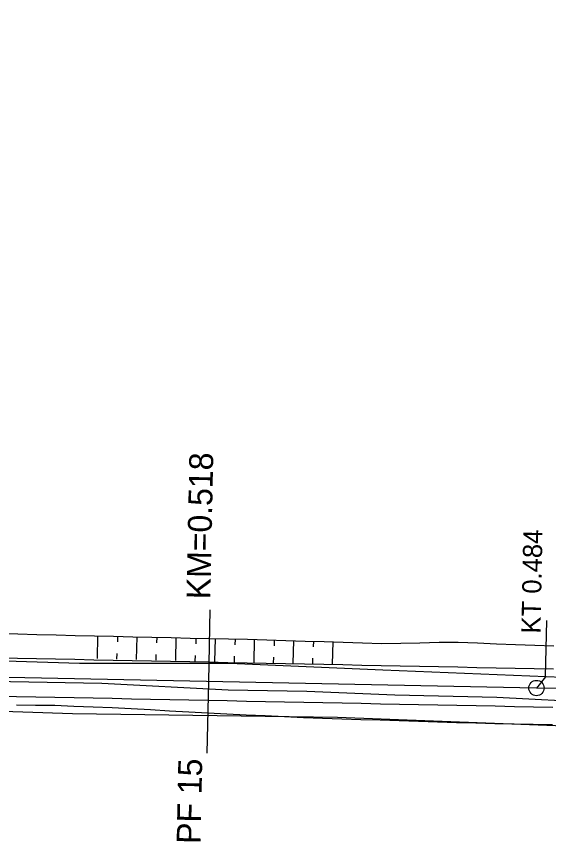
# Model space of a CAD drawing. Extents: x -478000 to -474772, y -1116940 to -1114124.
# Drawn here: x -477765.6 to -477710.1, y -1116657.5 to -1116571.3 of the extents above; entities that cross this region are included whole.
import ezdxf

# ---------------------------------------------------------------- set-up
doc = ezdxf.new("R2010")
doc.units = 0
for name, color, linetype in [('hrana_P', 7, 'Continuous'), ('L', 7, 'Continuous'), ('POLYGONY_SITUACE_PF', 7, 'Continuous'), ('POLYGONY_SITUACE_PF_POPISY', 7, 'Continuous'), ('POLYGONY_SITUACE_PO', 7, 'Continuous')]:
    doc.layers.add(name, color=color, linetype=linetype)

msp = doc.modelspace()

# ---------------------------------------------------------------- linework, layer by layer
for points in [[(-477710.3903956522, -1116640.33018744), (-477710.27233809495, -1116634.436584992)], [(-477710.3903956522, -1116640.33018744), (-477711.3429067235, -1116641.4972349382)]]:
    msp.add_lwpolyline(points)
at = {"layer": 'hrana_P'}
for p, q in [((-477765.65400000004, -1116643.2720000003), (-477763.65300000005, -1116643.287)), ((-477763.65300000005, -1116643.287), (-477761.65300000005, -1116643.2990000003)), ((-477761.65300000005, -1116643.2990000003), (-477759.655, -1116643.389)), ((-477759.655, -1116643.389), (-477757.656, -1116643.466)), ((-477757.656, -1116643.466), (-477755.657, -1116643.531)), ((-477755.657, -1116643.531), (-477753.65900000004, -1116643.642)), ((-477753.65900000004, -1116643.642), (-477751.66000000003, -1116643.755)), ((-477751.66000000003, -1116643.755), (-477749.662, -1116643.8660000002)), ((-477749.662, -1116643.8660000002), (-477747.66399999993, -1116643.975)), ((-477747.66399999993, -1116643.975), (-477745.666, -1116644.081)), ((-477745.666, -1116644.081), (-477743.66700000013, -1116644.186)), ((-477743.66700000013, -1116644.186), (-477741.669, -1116644.286)), ((-477741.669, -1116644.286), (-477739.67100000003, -1116644.386)), ((-477739.67100000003, -1116644.386), (-477737.672, -1116644.484)), ((-477737.672, -1116644.484), (-477735.673, -1116644.5620000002)), ((-477735.673, -1116644.5620000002), (-477733.6740000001, -1116644.6330000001)), ((-477733.6740000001, -1116644.6330000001), (-477731.6750000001, -1116644.703)), ((-477731.6750000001, -1116644.703), (-477729.67600000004, -1116644.7720000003)), ((-477729.67600000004, -1116644.7720000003), (-477727.677, -1116644.8390000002)), ((-477727.677, -1116644.8390000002), (-477725.67800000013, -1116644.905)), ((-477725.67800000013, -1116644.905), (-477723.6790000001, -1116644.969)), ((-477723.6790000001, -1116644.969), (-477721.68000000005, -1116645.031)), ((-477721.68000000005, -1116645.031), (-477719.68100000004, -1116645.0930000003)), ((-477719.68100000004, -1116645.0930000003), (-477717.68200000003, -1116645.151)), ((-477717.68200000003, -1116645.151), (-477715.68200000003, -1116645.209)), ((-477715.68200000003, -1116645.209), (-477713.683, -1116645.252)), ((-477713.683, -1116645.252), (-477711.683, -1116645.291)), ((-477711.683, -1116645.291), (-477709.6699999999, -1116645.3220000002))]:
    msp.add_line(p, q, dxfattribs=at)
for points in [[(-477767.504, -1116635.7890000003), (-477765.505, -1116635.842)], [(-477765.505, -1116635.842), (-477763.505, -1116635.896)], [(-477763.505, -1116635.896), (-477761.506, -1116635.948)], [(-477761.506, -1116635.948), (-477759.50700000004, -1116636)], [(-477759.50700000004, -1116636), (-477757.50700000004, -1116636.05)], [(-477757.50700000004, -1116636.05), (-477755.50800000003, -1116636.097)], [(-477757.2007821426, -1116638.425437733), (-477757.14059436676, -1116636.030824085)], [(-477755.50800000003, -1116636.097), (-477753.50800000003, -1116636.144)], [(-477755.09472800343, -1116636.08224622), (-477755.1097749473, -1116636.680899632)], [(-477753.50800000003, -1116636.144), (-477751.509, -1116636.1910000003)], [(-477753.1090494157, -1116638.528282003), (-477753.04886164, -1116636.133668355)], [(-477751.509, -1116636.1910000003), (-477749.509, -1116636.236)], [(-477751.00299527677, -1116636.18509049), (-477751.0180422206, -1116636.783743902)], [(-477749.509, -1116636.236), (-477747.51, -1116636.282)], [(-477749.017316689, -1116638.631126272), (-477748.95712891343, -1116636.236512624)], [(-477747.51, -1116636.282), (-477745.51, -1116636.326)], [(-477746.91126255, -1116636.287934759), (-477746.92630949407, -1116636.886588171)], [(-477745.51, -1116636.326), (-477743.511, -1116636.3660000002)], [(-477744.92558396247, -1116638.733970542), (-477744.86539618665, -1116636.339356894)], [(-477743.511, -1116636.3660000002), (-477741.51099999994, -1116636.406)], [(-477742.8195298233, -1116636.390779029), (-477742.8345767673, -1116636.9894324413)], [(-477741.51099999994, -1116636.406), (-477739.5120000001, -1116636.469)], [(-477740.8338512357, -1116638.836814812), (-477740.77366346, -1116636.442201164)], [(-477739.5120000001, -1116636.469), (-477737.51300000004, -1116636.531)], [(-477738.7277970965, -1116636.493623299), (-477738.7428440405, -1116637.0922767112)], [(-477737.51300000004, -1116636.531), (-477735.514, -1116636.5930000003)], [(-477736.74211850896, -1116638.939659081), (-477736.6819307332, -1116636.545045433)], [(-477735.514, -1116636.5930000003), (-477733.51500000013, -1116636.6540000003)], [(-477734.6360643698, -1116636.596467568), (-477734.65111131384, -1116637.19512098)], [(-477733.51500000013, -1116636.6540000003), (-477731.515, -1116636.7140000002)], [(-477732.6503857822, -1116639.042503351), (-477732.5901980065, -1116636.647889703)], [(-477731.515, -1116636.7140000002), (-477729.516, -1116636.774)], [(-477729.516, -1116636.774), (-477727.51699999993, -1116636.8330000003)], [(-477727.51699999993, -1116636.8330000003), (-477725.5160000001, -1116636.8160000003)], [(-477725.5160000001, -1116636.8160000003), (-477723.515, -1116636.7620000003)], [(-477723.515, -1116636.7620000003), (-477721.51300000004, -1116636.7070000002)], [(-477721.51300000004, -1116636.7070000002), (-477719.51300000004, -1116636.7080000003)], [(-477719.51300000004, -1116636.7080000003), (-477717.51400000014, -1116636.787)], [(-477717.51400000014, -1116636.787), (-477715.51500000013, -1116636.8660000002)], [(-477715.51500000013, -1116636.8660000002), (-477713.516, -1116636.944)], [(-477713.516, -1116636.944), (-477711.51800000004, -1116637.021)], [(-477711.51800000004, -1116637.021), (-477709.53400000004, -1116637.095)], [(-477765.55600000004, -1116638.411), (-477767.55600000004, -1116638.371)], [(-477763.5569999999, -1116638.451), (-477765.55600000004, -1116638.411)], [(-477761.55700000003, -1116638.4910000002), (-477763.5569999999, -1116638.451)], [(-477759.55700000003, -1116638.531), (-477761.55700000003, -1116638.4910000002)], [(-477757.558, -1116638.571), (-477759.55700000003, -1116638.531)], [(-477755.558, -1116638.611), (-477757.558, -1116638.571)], [(-477755.15491577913, -1116638.476859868), (-477755.1398688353, -1116637.878206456)], [(-477751.06318305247, -1116638.579704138), (-477751.04813610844, -1116637.981050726)], [(-477746.9714503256, -1116638.682548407), (-477746.9564033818, -1116638.0838949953)], [(-477742.879717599, -1116638.785392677), (-477742.86467065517, -1116638.1867392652)], [(-477738.78798487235, -1116638.888236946), (-477738.7729379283, -1116638.2895835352)], [(-477734.6962521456, -1116638.991081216), (-477734.6812052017, -1116638.392427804)], [(-477753.559, -1116638.651), (-477755.558, -1116638.611)], [(-477751.559, -1116638.6910000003), (-477753.559, -1116638.651)], [(-477749.5590000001, -1116638.7310000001), (-477751.559, -1116638.6910000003)], [(-477747.56, -1116638.771), (-477749.5590000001, -1116638.7310000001)], [(-477745.55999999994, -1116638.811), (-477747.56, -1116638.771)], [(-477743.5609999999, -1116638.851), (-477745.55999999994, -1116638.811)], [(-477741.56100000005, -1116638.892), (-477743.5609999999, -1116638.851)], [(-477739.56100000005, -1116638.932), (-477741.56100000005, -1116638.892)], [(-477737.56200000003, -1116638.972), (-477739.56100000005, -1116638.932)], [(-477735.56200000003, -1116639.0120000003), (-477737.56200000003, -1116638.972)], [(-477733.563, -1116639.0520000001), (-477735.56200000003, -1116639.0120000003)], [(-477731.563, -1116639.092), (-477733.563, -1116639.0520000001)], [(-477729.56300000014, -1116639.132), (-477731.563, -1116639.092)], [(-477727.564, -1116639.172), (-477729.56300000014, -1116639.132)], [(-477725.564, -1116639.212), (-477727.564, -1116639.172)], [(-477723.5650000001, -1116639.252), (-477725.564, -1116639.212)], [(-477721.565, -1116639.292), (-477723.5650000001, -1116639.252)], [(-477719.565, -1116639.3320000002), (-477721.565, -1116639.292)], [(-477717.56600000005, -1116639.372), (-477719.565, -1116639.3320000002)], [(-477715.5660000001, -1116639.412), (-477717.56600000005, -1116639.372)], [(-477713.56700000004, -1116639.452), (-477715.5660000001, -1116639.412)], [(-477711.5669999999, -1116639.492), (-477713.56700000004, -1116639.452)], [(-477709.574, -1116639.5290000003), (-477711.5669999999, -1116639.492)], [(-477765.63599999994, -1116642.4100000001), (-477767.6360000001, -1116642.3700000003)], [(-477763.63699999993, -1116642.45), (-477765.63599999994, -1116642.4100000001)], [(-477761.63700000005, -1116642.49), (-477763.63699999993, -1116642.45)], [(-477759.63800000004, -1116642.53), (-477761.63700000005, -1116642.49)], [(-477757.63800000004, -1116642.57), (-477759.63800000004, -1116642.53)], [(-477755.63800000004, -1116642.6100000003), (-477757.63800000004, -1116642.57)], [(-477753.639, -1116642.6500000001), (-477755.63800000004, -1116642.6100000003)], [(-477751.639, -1116642.69), (-477753.639, -1116642.6500000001)], [(-477749.64, -1116642.73), (-477751.639, -1116642.69)], [(-477747.64, -1116642.771), (-477749.64, -1116642.73)], [(-477745.64, -1116642.811), (-477747.64, -1116642.771)], [(-477743.6410000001, -1116642.851), (-477745.64, -1116642.811)], [(-477741.641, -1116642.891), (-477743.6410000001, -1116642.851)], [(-477739.64200000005, -1116642.9310000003), (-477741.641, -1116642.891)], [(-477737.64200000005, -1116642.971), (-477739.64200000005, -1116642.9310000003)], [(-477735.6420000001, -1116643.011), (-477737.64200000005, -1116642.971)], [(-477733.64300000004, -1116643.051), (-477735.6420000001, -1116643.011)], [(-477731.6429999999, -1116643.091), (-477733.64300000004, -1116643.051)], [(-477729.64400000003, -1116643.131), (-477731.6429999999, -1116643.091)], [(-477727.64400000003, -1116643.171), (-477729.64400000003, -1116643.131)], [(-477725.64400000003, -1116643.211), (-477727.64400000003, -1116643.171)], [(-477723.64500000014, -1116643.2510000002), (-477725.64400000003, -1116643.211)], [(-477721.645, -1116643.291), (-477723.64500000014, -1116643.2510000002)], [(-477719.646, -1116643.331), (-477721.645, -1116643.291)], [(-477717.646, -1116643.371), (-477719.646, -1116643.331)], [(-477715.646, -1116643.411), (-477717.646, -1116643.371)], [(-477713.647, -1116643.451), (-477715.646, -1116643.411)], [(-477711.64699999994, -1116643.492), (-477713.647, -1116643.451)], [(-477709.641, -1116643.5290000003), (-477711.64699999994, -1116643.492)]]:
    msp.add_lwpolyline(points, dxfattribs=at)
at = {"layer": 'L'}
for points in [[(-477822.03574678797, -1116639.5246735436), (-477820.897, -1116639.077), (-477817.125, -1116638.639), (-477804.88800000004, -1116638.219), (-477790.55500000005, -1116638.041), (-477775.668, -1116638.394), (-477759.069, -1116638.902), (-477743.411, -1116638.9100000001), (-477727.375, -1116639.612), (-477703.506, -1116640.58), (-477689.085, -1116640.739), (-477662.498, -1116640.639)], [(-477662.06200000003, -1116642.877), (-477676.23600000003, -1116643.067), (-477687.02, -1116643.1700000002), (-477697.63300000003, -1116643.0990000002), (-477704.81, -1116643.051), (-477715.494, -1116642.494), (-477726.12200000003, -1116642.2620000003), (-477735.31700000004, -1116641.85), (-477743.53400000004, -1116641.717), (-477756.732, -1116641.027), (-477766.265, -1116640.857), (-477778.44700000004, -1116640.4440000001), (-477788.169, -1116640.0050000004), (-477799.01300000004, -1116640.338), (-477806.00200000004, -1116640.405), (-477813.109, -1116640.341), (-477819.206, -1116640.6970000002), (-477820.85500000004, -1116641.0690000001), (-477822.30500000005, -1116642.0150000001)], [(-477619.515, -1116641.5785000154), (-477631.233, -1116645.709), (-477649.971, -1116646.3930000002), (-477673.38300000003, -1116646.6570000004), (-477700.23000000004, -1116645.8), (-477732.117, -1116644.5820000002), (-477759.787, -1116644.2), (-477782.63, -1116643.433), (-477804.353, -1116642.533), (-477816.493, -1116642.756), (-477821.58, -1116641.5420000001)]]:
    msp.add_lwpolyline(points, dxfattribs=at)
at = {"layer": 'POLYGONY_SITUACE_PF'}
msp.add_lwpolyline([(-477745.7195823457, -1116648.310123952), (-477745.5693764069, -1116640.811628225), (-477745.4191704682, -1116633.313132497)], dxfattribs=at)
at = {"layer": 'POLYGONY_SITUACE_PO'}
msp.add_lwpolyline([(-477500.70781559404, -1116571.337971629), (-477504.2169244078, -1116571.341618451), (-477507.59721562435, -1116572.283684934), (-477510.60239086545, -1116574.095529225), (-477513.0134838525, -1116576.645134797), (-477523.43050248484, -1116591.171911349), (-477530.00477229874, -1116599.187289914), (-477537.5603201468, -1116606.285248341), (-477545.97027502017, -1116612.3465993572), (-477555.0934189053, -1116617.269562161), (-477583.0835182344, -1116630.106284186), (-477594.8330191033, -1116634.7625948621), (-477607.0070808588, -1116638.15732904), (-477619.47066272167, -1116640.252830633), (-477632.0855124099, -1116641.025855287), (-477697.0704420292, -1116641.579382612), (-477701.8281190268, -1116641.597270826), (-477706.5857508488, -1116641.569887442), (-477711.3429067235, -1116641.4972349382), (-477819.96178678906, -1116639.321438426)], dxfattribs=at)
msp.add_circle((-477711.3429067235, -1116641.4972349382), 0.8, dxfattribs=at)

# ---------------------------------------------------------------- texts
msp.add_text('KT 0.484', height=2, rotation=88.85243442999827).set_placement((-477710.9239390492, -1116635.820347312))
at = {"layer": 'POLYGONY_SITUACE_PF_POPISY'}
for s, p in [('KM=0.518', (-477745.39777041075, -1116632.2448109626)), ('PF 15', (-477746.42226541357, -1116657.807787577))]:
    msp.add_text(s, height=2.5, rotation=88.85243443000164, dxfattribs=at).set_placement(p)

doc.saveas('drawing.dxf')
